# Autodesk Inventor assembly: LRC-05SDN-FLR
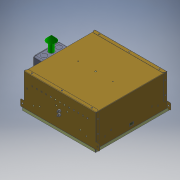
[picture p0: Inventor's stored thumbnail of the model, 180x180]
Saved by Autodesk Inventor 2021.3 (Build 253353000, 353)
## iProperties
Part Number: LRC-05SDN-FLR
Document SubType Name: Assembly
Designer: JChurch
Author: JChurch
load_classification: Lighting
motor: 0 ul
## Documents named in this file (6)
- X:\Revit Files\0000-Un-Zipped\COB\LRC-05SDN-FLR\LRC-05SDN-FLR.iam
- X:\INVENTOR\830\830399-00-00.ipt
- X:\INVENTOR\881\881088-00-00.iam
- X:\INVENTOR\KIRLIN_ENG\750\750032-00-XX.iam
- X:\INVENTOR\725\725377-00-00.ipt
- X:\Revit Files\0000-Un-Zipped\COB\LRC-05SDN-FLR\LRC-05SDN-FLR_Substitute_1.ipt
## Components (5 placed, 5 different names)
1. 830399-00-00:1 — Mate:1, Mate:2, Mate:3, Mate:4, Tangent:1, Angle:1, Insert:2
2. 881088-00-00:1 [sub-assembly] — Mate:4, Tangent:1, Angle:1
3. 750032-00-XX:1 [sub-assembly] — Insert:1, Insert:2
4. 725377-00-00:1 — Insert:1
5. LRC-05SDN-FLR_Substitute_1:1
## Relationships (8: Mate 4, Insert 2, Tangent 1, Angle 1)
- Mate:1: 830399-00-00:1
- Mate:2: 830399-00-00:1
- Mate:3: 830399-00-00:1
- Mate:4: 830399-00-00:1 ↔ 881088-00-00:1
- Tangent:1: 830399-00-00:1 ↔ 881088-00-00:1
- Angle:1: 830399-00-00:1 ↔ 881088-00-00:1
- Insert:1: 750032-00-XX:1 ↔ 725377-00-00:1
- Insert:2: 830399-00-00:1 ↔ 750032-00-XX:1
